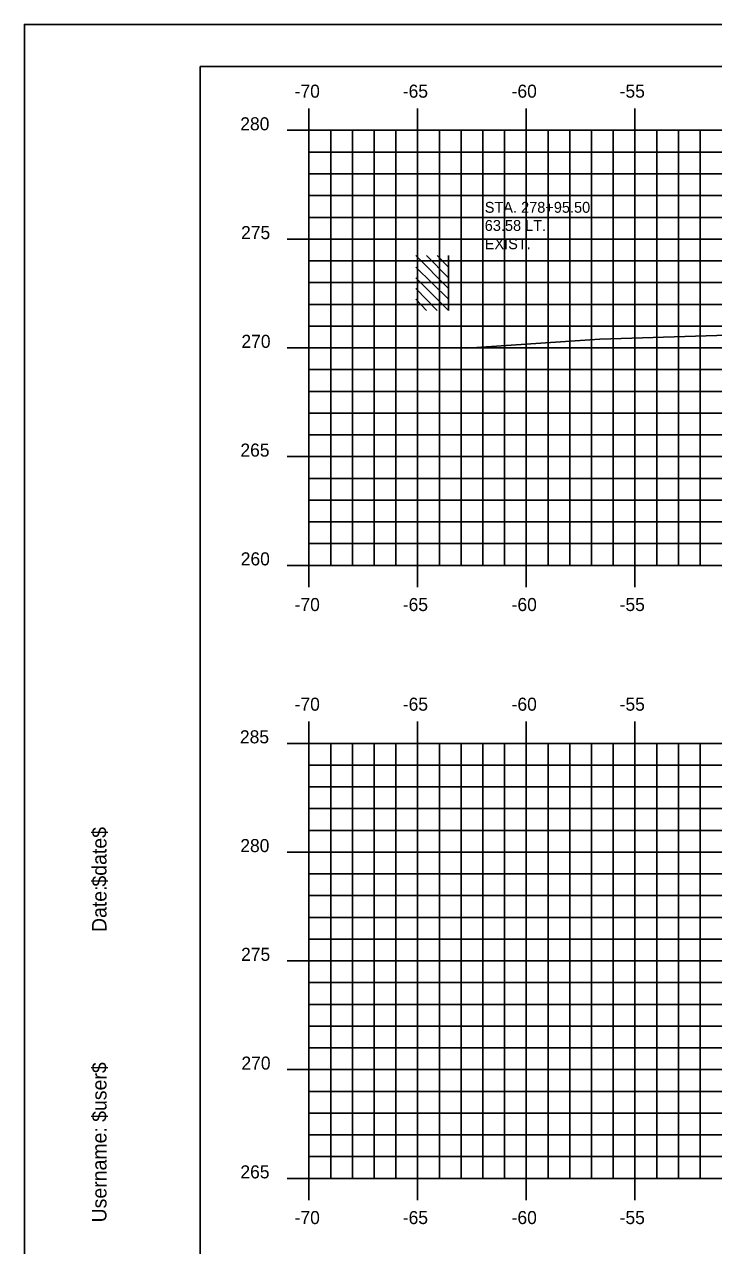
# Model space of a CAD drawing. Extents: x 854676 to 854846, y 366268 to 366378.
# Drawn here: x 854676 to 854707.7, y 366322 to 366378.2 of the extents above; entities that cross this region are included whole.
import ezdxf

# ---------------------------------------------------------------- set-up
doc = ezdxf.new("R2010")
doc.units = 0
for name, color, linetype in [('BORDER', 7, 'Continuous'), ('D_Text_Monospaced', 7, 'Continuous'), ('H_V ANNOTATION', 7, 'Continuous'), ('MAJOR', 7, 'Continuous'), ('MINOR', 7, 'Continuous'), ('PLOT BOUNDARY', 7, 'Continuous'), ('S_Buildings_SillElevation', 7, 'Continuous'), ('S_Roadway_Centerline', 7, 'Continuous')]:
    doc.layers.add(name, color=color, linetype=linetype)

msp = doc.modelspace()

# ---------------------------------------------------------------- linework, layer by layer
at = {"layer": 'BORDER'}
for p, q in [((854844.107, 366376.236), (854684.107, 366376.236)), ((854684.107, 366376.236), (854684.107, 366271.236))]:
    msp.add_line(p, q, dxfattribs=at)
at = {"layer": 'MAJOR'}
for p, q in [((854689.106, 366374.311), (854689.106, 366373.309)), ((854694.106, 366374.311), (854694.106, 366373.309)), ((854699.106, 366374.311), (854699.106, 366373.309)), ((854704.106, 366374.311), (854704.106, 366373.309)), ((854688.104, 366373.309), (854689.106, 366373.309)), ((854689.106, 366373.309), (854829.106, 366373.309)), ((854689.106, 366353.309), (854689.106, 366373.309)), ((854689.106, 366353.309), (854689.106, 366373.309)), ((854689.106, 366373.309), (854829.106, 366373.309)), ((854694.106, 366353.309), (854694.106, 366373.309)), ((854699.106, 366353.309), (854699.106, 366373.309)), ((854704.106, 366353.309), (854704.106, 366373.309)), ((854688.104, 366368.309), (854689.106, 366368.309)), ((854689.106, 366368.309), (854829.106, 366368.309)), ((854688.104, 366363.309), (854689.106, 366363.309)), ((854689.106, 366363.309), (854829.106, 366363.309)), ((854688.104, 366358.309), (854689.106, 366358.309)), ((854689.106, 366358.309), (854829.106, 366358.309)), ((854688.104, 366353.309), (854689.106, 366353.309)), ((854689.106, 366353.309), (854829.106, 366353.309)), ((854689.106, 366353.309), (854829.106, 366353.309)), ((854689.106, 366352.307), (854689.106, 366353.309)), ((854694.106, 366352.307), (854694.106, 366353.309)), ((854699.106, 366352.307), (854699.106, 366353.309)), ((854704.106, 366352.307), (854704.106, 366353.309)), ((854689.106, 366346.13), (854689.106, 366345.128)), ((854694.106, 366346.13), (854694.106, 366345.128)), ((854699.106, 366346.13), (854699.106, 366345.128)), ((854704.106, 366346.13), (854704.106, 366345.128)), ((854688.104, 366345.128), (854689.106, 366345.128)), ((854689.106, 366345.128), (854829.106, 366345.128)), ((854689.106, 366325.128), (854689.106, 366345.128)), ((854689.106, 366325.128), (854689.106, 366345.128)), ((854689.106, 366345.128), (854829.106, 366345.128)), ((854694.106, 366325.128), (854694.106, 366345.128)), ((854699.106, 366325.128), (854699.106, 366345.128)), ((854704.106, 366325.128), (854704.106, 366345.128)), ((854688.104, 366340.128), (854689.106, 366340.128)), ((854689.106, 366340.128), (854829.106, 366340.128)), ((854688.104, 366335.128), (854689.106, 366335.128)), ((854689.106, 366335.128), (854829.106, 366335.128)), ((854688.104, 366330.128), (854689.106, 366330.128)), ((854689.106, 366330.128), (854829.106, 366330.128)), ((854688.104, 366325.128), (854689.106, 366325.128)), ((854689.106, 366325.128), (854829.106, 366325.128)), ((854689.106, 366325.128), (854829.106, 366325.128)), ((854689.106, 366324.126), (854689.106, 366325.128)), ((854694.106, 366324.126), (854694.106, 366325.128)), ((854699.106, 366324.126), (854699.106, 366325.128)), ((854704.106, 366324.126), (854704.106, 366325.128))]:
    msp.add_line(p, q, dxfattribs=at)
at = {"layer": 'MINOR'}
for p, q in [((854690.106, 366353.309), (854690.106, 366373.309)), ((854691.106, 366353.309), (854691.106, 366373.309)), ((854692.106, 366353.309), (854692.106, 366373.309)), ((854693.106, 366353.309), (854693.106, 366373.309)), ((854695.106, 366353.309), (854695.106, 366373.309)), ((854696.106, 366353.309), (854696.106, 366373.309)), ((854697.106, 366353.309), (854697.106, 366373.309)), ((854698.106, 366353.309), (854698.106, 366373.309)), ((854700.106, 366353.309), (854700.106, 366373.309)), ((854701.106, 366353.309), (854701.106, 366373.309)), ((854702.106, 366353.309), (854702.106, 366373.309)), ((854703.106, 366353.309), (854703.106, 366373.309)), ((854705.106, 366353.309), (854705.106, 366373.309)), ((854706.106, 366353.309), (854706.106, 366373.309)), ((854707.106, 366353.309), (854707.106, 366373.309)), ((854689.106, 366372.309), (854829.106, 366372.309)), ((854689.106, 366372.309), (854690.108, 366372.309)), ((854689.106, 366371.309), (854829.106, 366371.309)), ((854689.106, 366371.309), (854690.108, 366371.309)), ((854689.106, 366370.309), (854829.106, 366370.309)), ((854689.106, 366370.309), (854690.108, 366370.309)), ((854689.106, 366369.309), (854829.106, 366369.309)), ((854689.106, 366369.309), (854690.108, 366369.309)), ((854689.106, 366367.309), (854829.106, 366367.309)), ((854689.106, 366367.309), (854690.108, 366367.309)), ((854689.106, 366366.309), (854829.106, 366366.309)), ((854689.106, 366366.309), (854690.108, 366366.309)), ((854689.106, 366365.309), (854829.106, 366365.309)), ((854689.106, 366365.309), (854690.108, 366365.309)), ((854689.106, 366364.309), (854829.106, 366364.309)), ((854689.106, 366364.309), (854690.108, 366364.309)), ((854689.106, 366362.309), (854829.106, 366362.309)), ((854689.106, 366362.309), (854690.108, 366362.309)), ((854689.106, 366361.309), (854829.106, 366361.309)), ((854689.106, 366361.309), (854690.108, 366361.309)), ((854689.106, 366360.309), (854829.106, 366360.309)), ((854689.106, 366360.309), (854690.108, 366360.309)), ((854689.106, 366359.309), (854829.106, 366359.309)), ((854689.106, 366359.309), (854690.108, 366359.309)), ((854689.106, 366357.309), (854829.106, 366357.309)), ((854689.106, 366357.309), (854690.108, 366357.309)), ((854689.106, 366356.309), (854829.106, 366356.309)), ((854689.106, 366356.309), (854690.108, 366356.309)), ((854689.106, 366355.309), (854829.106, 366355.309)), ((854689.106, 366355.309), (854690.108, 366355.309)), ((854689.106, 366354.309), (854829.106, 366354.309)), ((854689.106, 366354.309), (854690.108, 366354.309)), ((854690.106, 366325.128), (854690.106, 366345.128)), ((854691.106, 366325.128), (854691.106, 366345.128)), ((854692.106, 366325.128), (854692.106, 366345.128)), ((854693.106, 366325.128), (854693.106, 366345.128)), ((854695.106, 366325.128), (854695.106, 366345.128)), ((854696.106, 366325.128), (854696.106, 366345.128)), ((854697.106, 366325.128), (854697.106, 366345.128)), ((854698.106, 366325.128), (854698.106, 366345.128)), ((854700.106, 366325.128), (854700.106, 366345.128)), ((854701.106, 366325.128), (854701.106, 366345.128)), ((854702.106, 366325.128), (854702.106, 366345.128)), ((854703.106, 366325.128), (854703.106, 366345.128)), ((854705.106, 366325.128), (854705.106, 366345.128)), ((854706.106, 366325.128), (854706.106, 366345.128)), ((854707.106, 366325.128), (854707.106, 366345.128)), ((854689.106, 366344.128), (854829.106, 366344.128)), ((854689.106, 366344.128), (854690.108, 366344.128)), ((854689.106, 366343.128), (854829.106, 366343.128)), ((854689.106, 366343.128), (854690.108, 366343.128)), ((854689.106, 366342.128), (854829.106, 366342.128)), ((854689.106, 366342.128), (854690.108, 366342.128)), ((854689.106, 366341.128), (854829.106, 366341.128)), ((854689.106, 366341.128), (854690.108, 366341.128)), ((854689.106, 366339.128), (854829.106, 366339.128)), ((854689.106, 366339.128), (854690.108, 366339.128)), ((854689.106, 366338.128), (854829.106, 366338.128)), ((854689.106, 366338.128), (854690.108, 366338.128)), ((854689.106, 366337.128), (854829.106, 366337.128)), ((854689.106, 366337.128), (854690.108, 366337.128)), ((854689.106, 366336.128), (854829.106, 366336.128)), ((854689.106, 366336.128), (854690.108, 366336.128)), ((854689.106, 366334.128), (854829.106, 366334.128)), ((854689.106, 366334.128), (854690.108, 366334.128)), ((854689.106, 366333.128), (854829.106, 366333.128)), ((854689.106, 366333.128), (854690.108, 366333.128)), ((854689.106, 366332.128), (854829.106, 366332.128)), ((854689.106, 366332.128), (854690.108, 366332.128)), ((854689.106, 366331.128), (854829.106, 366331.128)), ((854689.106, 366331.128), (854690.108, 366331.128)), ((854689.106, 366329.128), (854829.106, 366329.128)), ((854689.106, 366329.128), (854690.108, 366329.128)), ((854689.106, 366328.128), (854829.106, 366328.128)), ((854689.106, 366328.128), (854690.108, 366328.128)), ((854689.106, 366327.128), (854829.106, 366327.128)), ((854689.106, 366327.128), (854690.108, 366327.128)), ((854689.106, 366326.128), (854829.106, 366326.128)), ((854689.106, 366326.128), (854690.108, 366326.128))]:
    msp.add_line(p, q, dxfattribs=at)
at = {"layer": 'PLOT BOUNDARY'}
msp.add_lwpolyline([(854676.013, 366268.177), (854846.013, 366268.177), (854846.013, 366378.177), (854676.013, 366378.177)], close=True, dxfattribs=at)
at = {"layer": 'S_Buildings_SillElevation'}
for p, q in [((854695.529, 366366.038), (854694.019, 366367.547)), ((854695.529, 366366.53), (854694.512, 366367.547)), ((854695.529, 366367.022), (854695.004, 366367.547)), ((854695.529, 366365.021), (854695.529, 366367.547)), ((854695.529, 366365.546), (854694.019, 366367.022)), ((854695.529, 366365.021), (854694.019, 366366.53)), ((854695.004, 366365.021), (854694.019, 366366.038)), ((854694.512, 366365.021), (854694.019, 366365.546))]:
    msp.add_line(p, q, dxfattribs=at)
at = {"layer": 'S_Roadway_Centerline'}
msp.add_lwpolyline([(854696.367, 366363.291), (854702.494, 366363.706), (854707.878, 366363.872), (854728.577, 366364.293), (854734.737, 366364.717), (854737.885, 366365.061), (854738.368, 366365.092), (854742.127, 366364.878), (854742.209, 366364.875), (854748.431, 366365.046), (854748.457, 366365.047), (854748.494, 366365.05), (854750.684, 366365.086), (854759.833, 366365.231), (854760.071, 366365.226), (854771.088, 366364.995)], dxfattribs=at)

# ---------------------------------------------------------------- texts
at = {"layer": 'BORDER'}
for s, p in [('$date$', (854679.791, 366338.542)), ('Date:', (854679.791, 366336.453)), ('$user$', (854679.791, 366327.728)), ('Username:', (854679.791, 366323.104))]:
    msp.add_text(s, height=0.6696, rotation=90, dxfattribs=at).set_placement(p)
at = {"layer": 'D_Text_Monospaced'}
for s, height, p in [('STA. 278+95.50', 0.49998, (854697.195, 366369.519)), ('63.58 LT.', 0.5, (854697.195, 366368.685)), ('EXIST. ', 0.5, (854697.195, 366367.845))]:
    msp.add_text(s, height=height, dxfattribs=at).set_placement(p)
at = {"layer": 'H_V ANNOTATION'}
for s, p in [('-70', (854688.448, 366374.809)), ('-65', (854693.424, 366374.809)), ('-60', (854698.432, 366374.809)), ('-55', (854703.402, 366374.809)), ('280', (854685.947, 366373.309)), ('275', (854685.984, 366368.309)), ('270', (854686, 366363.309)), ('265', (854685.952, 366358.309)), ('260', (854685.968, 366353.309)), ('-70', (854688.448, 366351.209)), ('-65', (854693.424, 366351.209)), ('-60', (854698.432, 366351.209)), ('-55', (854703.402, 366351.209)), ('-70', (854688.448, 366346.628)), ('-65', (854693.424, 366346.628)), ('-60', (854698.432, 366346.628)), ('-55', (854703.402, 366346.628)), ('285', (854685.931, 366345.128)), ('280', (854685.947, 366340.128)), ('275', (854685.984, 366335.128)), ('270', (854686, 366330.128)), ('265', (854685.952, 366325.128)), ('-70', (854688.448, 366323.028)), ('-65', (854693.424, 366323.028)), ('-60', (854698.432, 366323.028)), ('-55', (854703.402, 366323.028))]:
    msp.add_text(s, height=0.6, dxfattribs=at).set_placement(p)
at = {"layer": 'MAJOR'}
msp.add_text('-', height=0.00000006, rotation=53.1301, dxfattribs=at).set_placement((854689.102, 366353.309))

doc.saveas('drawing.dxf')
